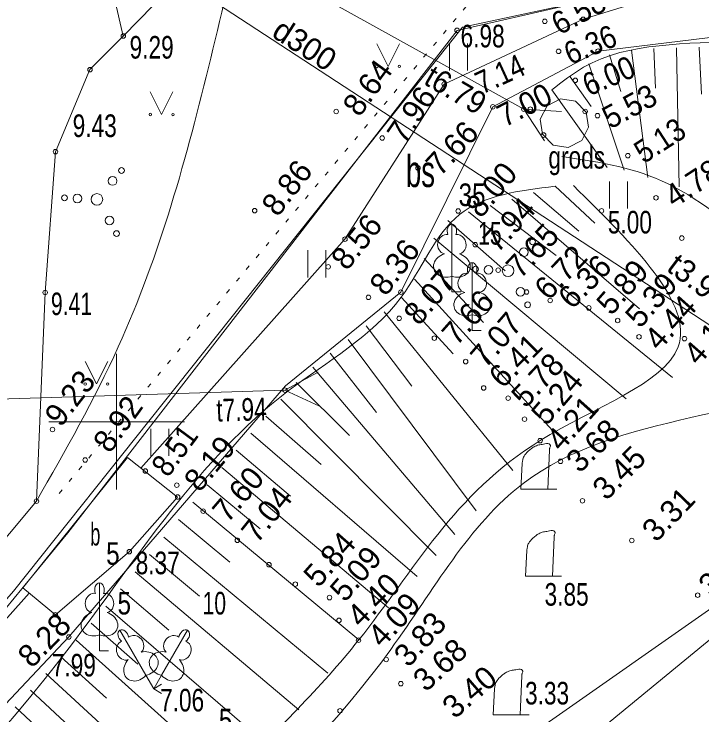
# Model space of a CAD drawing. Extents: x -1325 to -1182, y 698 to 905.
# Drawn here: x -1247.78 to -1232.55, y 814.1 to 829.61 of the extents above; entities that cross this region are included whole.
import ezdxf
from ezdxf.enums import TextEntityAlignment as Align

# ---------------------------------------------------------------- set-up
doc = ezdxf.new("R2010")
doc.units = 0
doc.header["$LTSCALE"] = 0.2
doc.linetypes.add('DOTTED', pattern=[1.5, 0.3, -1.2])
for name, color, linetype, lineweight in [('1', 7, 'Continuous', 13), ('19', 7, 'Continuous', 13), ('20', 7, 'Continuous', 13), ('25', 7, 'Continuous', 13), ('28', 7, 'Continuous', 13), ('3', 7, 'Continuous', 13), ('30', 7, 'Continuous', 13), ('5', 7, 'Continuous', 13), ('55', 7, 'Continuous', 13), ('56', 7, 'Continuous', 13), ('57', 7, 'DOTTED', 13), ('6', 7, 'Continuous', 13), ('61', 7, 'Continuous', 13), ('62', 7, 'Continuous', 13), ('63', 7, 'Continuous', 13)]:
    doc.layers.add(name, color=color, linetype=linetype, lineweight=lineweight)
for name, color, linetype in [('10', 7, 'Continuous'), ('11', 7, 'Continuous'), ('12', 7, 'Continuous'), ('15', 7, 'Continuous'), ('8', 7, 'Continuous')]:
    doc.layers.add(name, color=color, linetype=linetype)

msp = doc.modelspace()

# ---------------------------------------------------------------- linework, layer by layer
at = {"layer": '1'}
for p, q in [((-1232.61, 828.877), (-1232.555, 827.84)), ((-1234.108, 828.809), (-1233.743, 825.994)), ((-1233.61, 828.848), (-1233.572, 827.973)), ((-1233.11, 828.861), (-1233.048, 825.784)), ((-1234.597, 828.707), (-1234.344, 827.894)), ((-1235.054, 828.507), (-1234.27, 826.156)), ((-1235.464, 828.221), (-1234.996, 827.565)), ((-1235.871, 827.931), (-1234.647, 826.214)), ((-1235.8, 825.801), (-1234.915, 824.985)), ((-1236.279, 825.658), (-1235.273, 824.806)), ((-1236.759, 825.516), (-1233.93, 823.086)), ((-1237.238, 825.374), (-1235.774, 824.268)), ((-1237.717, 825.232), (-1233.202, 821.568)), ((-1238.174, 825.038), (-1236.902, 823.928)), ((-1238.484, 824.65), (-1234.223, 821.091)), ((-1238.698, 824.198), (-1237.386, 822.781)), ((-1238.909, 823.745), (-1235.857, 820.396)), ((-1239.204, 823.344), (-1238.057, 822.089)), ((-1239.582, 823.017), (-1236.734, 819.506)), ((-1239.977, 822.71), (-1238.97, 821.376)), ((-1240.377, 822.41), (-1237.543, 818.611)), ((-1240.776, 822.108), (-1239.755, 820.789)), ((-1241.164, 821.793), (-1238.014, 818.089)), ((-1241.531, 821.454), (-1240.352, 820.279)), ((-1241.871, 821.087), (-1238.431, 817.627)), ((-1242.202, 820.713), (-1240.977, 819.642)), ((-1242.53, 820.335), (-1238.851, 817.163)), ((-1242.855, 819.955), (-1241.653, 818.937)), ((-1243.177, 819.573), (-1239.485, 816.469)), ((-1243.498, 819.19), (-1242.327, 818.214)), ((-1243.818, 818.805), (-1240.142, 815.757)), ((-1244.137, 818.42), (-1242.998, 817.476)), ((-1244.456, 818.035), (-1240.825, 815.021)), ((-1244.776, 817.651), (-1243.669, 816.729)), ((-1245.096, 817.267), (-1241.467, 814.213)), ((-1245.419, 816.885), (-1244.345, 815.976)), ((-1245.744, 816.505), (-1242.223, 813.478)), ((-1246.071, 816.127), (-1245.031, 815.219)), ((-1246.402, 815.752), (-1242.999, 812.703)), ((-1246.737, 815.381), (-1245.726, 814.465)), ((-1247.073, 815.011), (-1243.736, 811.955)), ((-1247.411, 814.643), (-1246.417, 813.726)), ((-1247.751, 814.276), (-1244.454, 811.216))]:
    msp.add_line(p, q, dxfattribs=at)
for points in [[(-1235.871, 827.931), (-1235.166, 828.433), (-1231.672, 829.028), (-1224.12, 831.442)], [(-1235.8, 825.801), (-1237.913, 825.174), (-1239.202, 823.346), (-1241.709, 821.268), (-1246.557, 815.58), (-1256.525, 805.053), (-1260.591, 799.146), (-1261.416, 795.29), (-1262.741, 791.444), (-1262.206, 785.139)]]:
    msp.add_spline(points, degree=3, dxfattribs=at)
at = {"layer": '19'}
msp.add_spline([(-1253.457, 785.393), (-1253.726, 794.104), (-1251.637, 801.373), (-1250.122, 804.26), (-1247.608, 807.348), (-1239.437, 815.544), (-1236.507, 819.221), (-1228.799, 821.851), (-1223.357, 826.161), (-1220.079, 827.95)], degree=3, dxfattribs=at)
at = {"layer": '20'}
msp.add_lwpolyline([(-1251.428, 785.238), (-1264.287, 784.95), (-1270.386, 788.761), (-1278.142, 789.522), (-1278.429, 820.375), (-1260.691, 834.371), (-1258.18, 840.695), (-1250.014, 845.483), (-1229.719, 840.991), (-1227.82, 835.408), (-1218.991, 825.806), (-1239.144, 811.691), (-1246.245, 803.625), (-1250.023, 795.415), (-1251.371, 785.664)], close=True, dxfattribs=at)
at = {"layer": '25'}
for points in [[(-1245.505, 822.086), (-1245.505, 820.586), (-1245.505, 819.086)], [(-1245.505, 822.086), (-1245.505, 820.586), (-1245.505, 819.086)], [(-1247.005, 820.586), (-1245.505, 820.586), (-1244.005, 820.586)], [(-1247.005, 820.586), (-1245.505, 820.586), (-1244.005, 820.586)]]:
    msp.add_lwpolyline(points, dxfattribs=at)
at = {"layer": '28'}
for points in [[(-1235.654, 827.452), (-1236.491, 827.506), (-1236.032, 826.804)], [(-1241.04, 821.682), (-1241.778, 821.284), (-1241.016, 820.933)]]:
    msp.add_lwpolyline(points, dxfattribs=at)
at = {"layer": '3'}
for p, q in [((-1236.491, 827.506), (-1257.833, 839.343)), ((-1232.369, 822.724), (-1257.833, 839.343)), ((-1251.16, 820.99), (-1241.778, 821.284))]:
    msp.add_line(p, q, dxfattribs=at)
at = {"layer": '30'}
msp.add_spline([(-1247.278, 818.829), (-1245.467, 822.244), (-1243.42, 828.633), (-1242.662, 831.887)], degree=3, dxfattribs=at)
at = {"layer": '5'}
for p, q in [((-1238.136, 828.361), (-1238.136, 828.961)), ((-1237.736, 828.361), (-1237.736, 828.961)), ((-1234.594, 825.307), (-1234.594, 825.907)), ((-1234.194, 825.307), (-1234.194, 825.907)), ((-1238.083, 824.961), (-1238.083, 823.808)), ((-1237.993, 824.729), (-1237.994, 824.729)), ((-1241.27, 823.783), (-1241.27, 824.383)), ((-1240.87, 823.783), (-1240.87, 824.383)), ((-1237.633, 824.107), (-1237.633, 822.954)), ((-1238.083, 823.808), (-1238.083, 823.461)), ((-1237.543, 823.875), (-1237.544, 823.875)), ((-1238.083, 823.461), (-1237.883, 823.461)), ((-1237.633, 822.954), (-1237.633, 822.607)), ((-1237.633, 822.607), (-1237.433, 822.607)), ((-1244.748, 819.833), (-1244.748, 820.433)), ((-1244.348, 819.833), (-1244.348, 820.433)), ((-1235.958, 819.092), (-1235.924, 819.957)), ((-1235.958, 819.092), (-1236.558, 819.092)), ((-1235.958, 819.092), (-1235.758, 819.092)), ((-1235.855, 817.167), (-1235.821, 818.032)), ((-1235.855, 817.167), (-1236.455, 817.167)), ((-1235.855, 817.167), (-1235.655, 817.167)), ((-1245.884, 817.019), (-1245.884, 815.866)), ((-1245.794, 816.787), (-1245.795, 816.787)), ((-1245.884, 815.866), (-1245.884, 815.519)), ((-1245.432, 815.973), (-1244.855, 814.974)), ((-1243.932, 815.973), (-1244.508, 814.974)), ((-1245.238, 815.817), (-1245.239, 815.817)), ((-1243.97, 815.727), (-1243.971, 815.728)), ((-1245.884, 815.519), (-1245.684, 815.519)), ((-1244.855, 814.974), (-1244.682, 814.674)), ((-1244.508, 814.974), (-1244.682, 814.674)), ((-1236.571, 814.1), (-1236.537, 814.965)), ((-1244.682, 814.674), (-1244.508, 814.774)), ((-1244.682, 814.674), (-1244.508, 814.574)), ((-1236.571, 814.1), (-1237.171, 814.1)), ((-1236.571, 814.1), (-1236.371, 814.1))]:
    msp.add_line(p, q, dxfattribs=at)
for points in [[(-1239.744, 828.953), (-1239.494, 828.453), (-1239.244, 828.953)], [(-1244.758, 827.887), (-1244.508, 827.387), (-1244.258, 827.887)], [(-1246.199, 821.922), (-1245.949, 821.422), (-1245.699, 821.922)], [(-1236.527, 819.665), (-1236.558, 819.092), (-1236.258, 819.092), (-1235.958, 819.092)], [(-1236.424, 817.74), (-1236.455, 817.167), (-1236.155, 817.167), (-1235.855, 817.167)], [(-1237.14, 814.673), (-1237.171, 814.1), (-1236.871, 814.1), (-1236.571, 814.1)]]:
    msp.add_lwpolyline(points, dxfattribs=at)
for centre, radius in [((-1239.7443, 828.4521), 0.028), ((-1239.2443, 828.4521), 0.0263), ((-1244.758, 827.3861), 0.028), ((-1244.258, 827.3861), 0.0263), ((-1245.3956, 826.1473), 0.064), ((-1245.5921, 825.9156), 0.096), ((-1246.3735, 825.5288), 0.096), ((-1245.9396, 825.508), 0.128), ((-1246.658, 825.5422), 0.064), ((-1245.6631, 825.0411), 0.096), ((-1245.5057, 824.7518), 0.064), ((-1236.2956, 824.5693), 0.064), ((-1236.4921, 824.3376), 0.096), ((-1237.558, 823.9642), 0.064), ((-1237.2735, 823.9508), 0.096), ((-1236.8396, 823.93), 0.128), ((-1236.5631, 823.4631), 0.096), ((-1236.4057, 823.1738), 0.064), ((-1246.1994, 821.4212), 0.028), ((-1245.6994, 821.4212), 0.0263)]:
    msp.add_circle(centre, radius, dxfattribs=at)
for centre, major_axis, ratio, start_param, end_param in [((-1238.0822, 824.811), (0, -0.1499), 0.707107, 3.1453698, 5.2874846), ((-1238.083, 824.811), (0, -0.1499), 0.707107, 0.9957007, 3.1378155), ((-1238.2109, 824.5162), (-0.0387, -0.2124), 0.861323, 3.1415927, 6.2831853), ((-1237.9543, 824.5162), (0.0387, -0.2124), 0.861323, 6.2831853, 9.424778), ((-1238.1722, 824.0539), (0.3068, 0.0951), 0.814445, 1.5707963, 4.7520146), ((-1237.993, 824.0539), (-0.3068, 0.0951), 0.814445, 1.5311707, 4.712389), ((-1237.6322, 823.957), (0, -0.1499), 0.707107, 3.1453698, 5.2874846), ((-1237.633, 823.957), (0, -0.1499), 0.707107, 0.9957007, 3.1378155), ((-1237.7609, 823.6622), (-0.0387, -0.2124), 0.861323, 3.1415927, 6.2831853), ((-1237.5043, 823.6622), (0.0387, -0.2124), 0.861323, 6.2831853, 9.424778), ((-1237.7222, 823.1999), (0.3068, 0.0951), 0.814445, 1.5707963, 4.7520146), ((-1237.543, 823.1999), (-0.3068, 0.0951), 0.814445, 1.5311707, 4.712389), ((-1245.8832, 816.869), (0, -0.1499), 0.707107, 3.1453698, 5.2874846), ((-1245.884, 816.869), (0, -0.1499), 0.707107, 0.9957007, 3.1378155), ((-1246.0119, 816.5742), (-0.0387, -0.2124), 0.861323, 3.1415927, 6.2831853), ((-1245.7553, 816.5742), (0.0387, -0.2124), 0.861323, 6.2831853, 9.424778), ((-1245.9732, 816.1119), (0.3068, 0.0951), 0.814445, 1.5707963, 4.7520146), ((-1245.794, 816.1119), (-0.3068, 0.0951), 0.814445, 1.5311707, 4.712389), ((-1245.3563, 815.8434), (0.075, -0.1298), 0.707107, 3.1453698, 5.2874846), ((-1245.357, 815.843), (0.075, -0.1298), 0.707107, 0.9957007, 3.1378155), ((-1245.0981, 815.6519), (0.1397, -0.1646), 0.861323, 6.2831853, 9.424778), ((-1244.2651, 815.6519), (-0.1397, -0.1646), 0.861323, 3.1415927, 6.2831853), ((-1244.0062, 815.843), (-0.075, -0.1298), 0.707107, 3.1453698, 5.2874846), ((-1244.0069, 815.8434), (-0.075, -0.1298), 0.707107, 0.9957007, 3.1378155), ((-1245.3203, 815.5236), (0.0727, -0.2033), 0.861323, 3.1415927, 6.2831853), ((-1244.0429, 815.5236), (-0.0727, -0.2033), 0.861323, 6.2831853, 9.424778), ((-1244.9005, 815.2322), (-0.3133, -0.071), 0.814445, 1.5311707, 4.712389), ((-1244.4627, 815.2322), (0.3133, -0.071), 0.814445, 1.5707963, 4.7520146), ((-1245.0556, 815.1427), (0.2182, 0.2358), 0.814445, 1.5707963, 4.7520146), ((-1244.3076, 815.1427), (-0.2182, 0.2358), 0.814445, 1.5311707, 4.712389)]:
    msp.add_ellipse(centre, major_axis=major_axis, ratio=ratio, start_param=start_param, end_param=end_param, dxfattribs=at)
for points in [[(-1235.924, 819.957), (-1235.92, 819.988), (-1235.917, 819.999), (-1235.902, 820.061), (-1235.932, 820.096), (-1236.054, 820.09), (-1236.158, 820.072), (-1236.264, 820.033), (-1236.329, 819.989), (-1236.404, 819.925), (-1236.484, 819.827), (-1236.515, 819.738), (-1236.527, 819.664)], [(-1235.821, 818.032), (-1235.817, 818.063), (-1235.814, 818.074), (-1235.799, 818.136), (-1235.829, 818.171), (-1235.951, 818.165), (-1236.055, 818.147), (-1236.161, 818.108), (-1236.226, 818.064), (-1236.301, 818), (-1236.381, 817.902), (-1236.412, 817.813), (-1236.424, 817.739)], [(-1236.537, 814.965), (-1236.533, 814.996), (-1236.53, 815.007), (-1236.515, 815.069), (-1236.545, 815.104), (-1236.667, 815.098), (-1236.771, 815.08), (-1236.877, 815.041), (-1236.942, 814.997), (-1237.017, 814.933), (-1237.097, 814.835), (-1237.128, 814.746), (-1237.14, 814.672)]]:
    msp.add_spline(points, degree=3, dxfattribs=at)
at = {"layer": '55'}
for points in [[(-1279.322, 790.175), (-1264.692, 791.666), (-1263.121, 794.463), (-1263.06, 799.299), (-1247.785, 816.834), (-1237.845, 829.32), (-1225.799, 831.912), (-1223.768, 834.184)], [(-1251.177, 781.942), (-1250.876, 788.586), (-1249.424, 796.058), (-1246.365, 802.296), (-1239.008, 810.653), (-1237.317, 812.435), (-1234.783, 813.781), (-1227.269, 819.96), (-1220.231, 823.644), (-1218.172, 824.289), (-1214.858, 828.794), (-1213.693, 830.709)]]:
    msp.add_lwpolyline(points, dxfattribs=at)
at = {"layer": '56'}
msp.add_line((-1245.26, 819.794), (-1247.583, 816.91), dxfattribs=at)
msp.add_lwpolyline([(-1236.13, 827.282), (-1236.079, 826.949), (-1235.841, 826.711), (-1235.509, 826.657), (-1235.209, 826.809), (-1235.055, 827.108), (-1235.107, 827.441), (-1235.344, 827.679), (-1235.676, 827.733), (-1235.976, 827.581)], close=True, dxfattribs=at)
msp.add_lwpolyline([(-1247.583, 816.91), (-1246.86, 816.313), (-1245.222, 817.711), (-1244.154, 818.919), (-1245.26, 819.794)], dxfattribs=at)
at = {"layer": '57'}
msp.add_line((-1246.776, 819.001), (-1237.687, 829.874), dxfattribs=at)
at = {"layer": '6'}
for centre in [(-1236.0266, 829.451), (-1235.1756, 829.494), (-1237.9676, 829.25), (-1245.3566, 829.125), (-1235.7206, 828.787), (-1234.8476, 828.79), (-1246.0946, 828.381), (-1238.2536, 828.059), (-1235.3496, 828.143), (-1240.6428, 827.4525), (-1237.1766, 827.558), (-1236.4906, 827.506), (-1236.3476, 827.505), (-1235.1306, 827.454), (-1234.8596, 827.361), (-1239.6246, 826.867), (-1236.0526, 826.932), (-1246.8576, 826.564), (-1234.1866, 826.477), (-1238.8336, 826.202), (-1233.5636, 825.544), (-1242.4467, 825.2599), (-1234.7696, 825.254), (-1237.9436, 825.251), (-1232.9936, 824.652), (-1240.4496, 824.627), (-1237.5656, 824.505), (-1240.8196, 824.015), (-1237.0586, 823.942), (-1247.0876, 823.447), (-1239.2136, 823.453), (-1236.4296, 823.457), (-1239.9296, 823.339), (-1235.9086, 823.272), (-1235.0506, 823.106), (-1239.2506, 822.875), (-1234.4136, 822.826), (-1233.94, 822.4657), (-1238.4716, 822.438), (-1232.9346, 822.426), (-1237.7766, 821.918), (-1241.7776, 821.284), (-1237.3806, 821.335), (-1236.8386, 821.11), (-1236.4736, 820.643), (-1246.9227, 820.4132), (-1236.1286, 820.169), (-1246.1996, 819.741), (-1235.6786, 819.709), (-1244.8686, 819.496), (-1244.1726, 819.181), (-1244.1536, 818.919), (-1247.2776, 818.829), (-1235.1926, 818.837), (-1243.5866, 818.608), (-1242.8326, 817.963), (-1234.0995, 817.9588), (-1245.2216, 817.711), (-1242.1326, 817.423), (-1241.5486, 816.992), (-1232.6418, 816.746), (-1240.7916, 816.694), (-1246.8596, 816.313), (-1240.5826, 816.192), (-1246.5636, 815.823), (-1240.1486, 815.75), (-1239.5366, 815.325), (-1239.2126, 814.788), (-1240.5586, 814.189)]:
    msp.add_circle(centre, 0.05, dxfattribs=at)
at = {"layer": '61'}
msp.add_lwpolyline([(-1249.819, 814.203), (-1246.581, 818.124), (-1237.968, 829.25), (-1225.679, 832.058)], dxfattribs=at)
at = {"layer": '62'}
for points in [[(-1220.798, 828.526), (-1224.038, 826.583), (-1229.102, 823.322), (-1233.445, 825.922), (-1235.652, 826.457)], [(-1254.434, 786.21), (-1255.853, 794.247), (-1253.372, 799.782), (-1252.196, 801.907), (-1252.102, 801.965), (-1250.675, 804.058), (-1247.791, 807.511), (-1245.419, 810.213), (-1244.186, 811.494), (-1242.939, 812.763), (-1240.149, 815.75), (-1236.129, 820.169), (-1233.075, 822.242), (-1235.394, 825.816)]]:
    msp.add_spline(points, degree=3, dxfattribs=at)
at = {"layer": '63'}
msp.add_line((-1245.357, 829.125), (-1246.012, 831.935), dxfattribs=at)
for points in [[(-1256.412, 818.123), (-1256.201, 815.29), (-1252.408, 813.098), (-1251.504, 813.774), (-1247.278, 818.829), (-1247.088, 823.447), (-1246.858, 826.564), (-1246.095, 828.381), (-1245.357, 829.125), (-1242.02, 832.546), (-1243.096, 833.394)], [(-1225.119, 832.074), (-1232.655, 830.279), (-1235.176, 829.494), (-1238.254, 828.059), (-1240.45, 824.627), (-1244.966, 819.561)], [(-1265.079, 785.987), (-1263.807, 789.442), (-1261.536, 795.397), (-1260.86, 799.605), (-1256.627, 805.136), (-1246.564, 815.823), (-1241.769, 821.378), (-1239.214, 823.453), (-1237.177, 827.558), (-1234.848, 828.79), (-1231.517, 829.195), (-1224.557, 831.447)], [(-1247.437, 816.79), (-1257.209, 805.83), (-1262.318, 799.97), (-1262.654, 795.375), (-1263.503, 792.223), (-1265.015, 790.631), (-1268.643, 788.504)]]:
    msp.add_lwpolyline(points, dxfattribs=at)

# ---------------------------------------------------------------- texts
at = {"layer": '10', "width": 0.65}
msp.add_text('bs', height=0.7, dxfattribs=at).set_placement((-1238.778, 825.782), align=Align.CENTER)
at = {"layer": '11'}
for s, rotation, p in [('d300', 327.224, (-1241.4748, 828.7245)), ('t3.99', 323.042, (-1232.7643, 823.5016))]:
    msp.add_text(s, height=0.5, rotation=rotation, dxfattribs=at).set_placement(p, align=Align.CENTER)
for s, rotation, width, p in [('t6.79', 329.713, 0.95, (-1238.1241, 827.7192)), ('t7.94', 1.795, 0.75, (-1242.7318, 820.6057))]:
    msp.add_text(s, height=0.5, rotation=rotation, dxfattribs=dict(at, width=width)).set_placement(p, align=Align.CENTER)
at = {"layer": '12'}
for s, width, p in [(' 35', 0.8, (-1238.082, 825.361)), (' 15', 0.7, (-1237.632, 824.507)), (' 5', 0.8, (-1245.884, 817.419)), (' 5', 0.8, (-1245.632, 816.32)), (' 10', 0.7, (-1243.732, 816.32)), (' 5', 0.8, (-1243.389, 813.733))]:
    msp.add_text(s, height=0.5, dxfattribs=dict(at, width=width)).set_placement(p)
at = {"layer": '15'}
for s, width, p in [('grods', 0.75, (-1235.946, 826.191)), ('b', 0.6, (-1246.087, 817.847))]:
    msp.add_text(s, height=0.5, dxfattribs=dict(at, width=width)).set_placement(p)
at = {"layer": '8'}
for s, rotation, width, p in [(' 6.58', 28.573, 0.95, (-1235.857, 829.05)), (' 6.36', 22.605, 0.9, (-1235.618, 828.414)), (' 7.14', 24.653, 0.85, (-1237.559, 827.761)), (' 6.00', 23.171, 0.9, (-1235.206, 827.719)), (' 7.00', 26.785, 0.95, (-1237.074, 827.02)), (' 5.53', 28.383, 0.95, (-1234.732, 826.97)), (' 5.13', 32.929, 0.9, (-1233.976, 826.195)), (' 8.51', 53.571, 0.9, (-1244.466, 819.199))]:
    msp.add_text(s, height=0.5, rotation=rotation, dxfattribs=dict(at, width=width)).set_placement(p)
for s, width, p in [(' 6.98', 0.75, (-1238.029, 828.873)), (' 9.29', 0.75, (-1245.356, 828.625)), (' 9.43', 0.75, (-1246.616, 826.889)), (' 5.00', 0.75, (-1234.77, 824.754)), (' 9.41', 0.7, (-1247.088, 822.947)), (' 8.37', 0.75, (-1245.222, 817.211)), (' 3.85', 0.75, (-1236.17, 816.515)), (' 7.99', 0.75, (-1247.078, 814.948)), (' 3.33', 0.75, (-1236.603, 814.328)), (' 7.06', 0.75, (-1244.682, 814.174))]:
    msp.add_text(s, height=0.5, dxfattribs=dict(at, width=width)).set_placement(p)
for s, rotation, p in [(' 8.64', 54.068, (-1240.238, 827.159)), (' 7.96', 55.761, (-1239.242, 826.554)), (' 7.66', 47.113, (-1238.467, 825.862)), (' 8.86', 52.091, (-1242.052, 824.953)), (' 8.00', 49.596, (-1237.563, 824.927)), (' 4.78', 32.959, (-1233.319, 825.205)), (' 7.94', 47.399, (-1237.198, 824.166)), (' 8.56', 51.117, (-1240.524, 823.764)), (' 7.65', 46.428, (-1236.696, 823.597)), (' 8.36', 53.061, (-1239.655, 823.194)), (' 6.72', 46.62, (-1236.066, 823.114)), (' 6.36', 45.409, (-1235.552, 822.921)), (' 5.89', 48.667, (-1234.675, 822.776)), (' 8.07', 49.339, (-1238.934, 822.549)), (' 5.39', 48.224, (-1234.041, 822.493)), (' 7.66', 48.488, (-1238.097, 822.107)), (' 4.44', 48.23, (-1233.618, 821.995)), (' 7.07', 49.117, (-1237.461, 821.606)), (' 4.12', 48.698, (-1232.746, 821.668)), (' 6.41', 45.177, (-1237.088, 821.17)), (' 5.78', 46.68, (-1236.577, 820.731)), (' 9.23', 52.106, (-1246.855, 820.298)), (' 5.24', 49.445, (-1236.109, 820.334)), (' 8.92', 54.249, (-1245.763, 819.714)), (' 4.21', 48.26, (-1235.786, 819.765)), (' 3.68', 43.888, (-1235.39, 819.3)), (' 8.19', 50.227, (-1243.788, 818.861)), (' 3.45', 45.114, (-1234.795, 818.69)), (' 7.60', 49.585, (-1243.167, 818.184)), (' 7.04', 51.541, (-1242.506, 817.725)), (' 3.31', 46.023, (-1233.69, 817.764)), (' 5.84', 48.52, (-1241.158, 816.754)), (' 5.09', 49.117, (-1240.57, 816.429)), (' 3.42', 41.398, (-1232.483, 816.565)), (' 4.40', 45.407, (-1240.226, 815.872)), (' 4.09', 46.86, (-1239.752, 815.424)), (' 8.28', 45.877, (-1247.509, 814.978)), (' 3.83', 47.809, (-1239.166, 814.989)), (' 3.68', 42.198, (-1238.796, 814.462)), (' 3.40', 40.947, (-1238.16, 813.869))]:
    msp.add_text(s, height=0.5, rotation=rotation, dxfattribs=at).set_placement(p)

doc.saveas('drawing.dxf')
